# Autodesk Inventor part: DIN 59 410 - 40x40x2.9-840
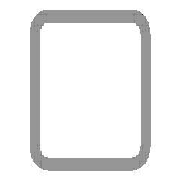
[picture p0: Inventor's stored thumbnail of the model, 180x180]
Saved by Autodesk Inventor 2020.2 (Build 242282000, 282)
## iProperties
Manager: www.cadconsulting.pl
Company: Fabian Stasiak CAD Consulting
_CCFamilyMember: 10
_CCFamilyDisplayName: DIN 59410 (Kwadrat) - Rurki stalowe o przekroju kwadratowym formowane na gorąco
_FrameMemberDoc: Frame Member File
_Version: 15.0.0
_GetPNFromCC: 1
Created: 2015-01
Part Number: DIN 59 410 - 40x40x2.9-840
Material: Stal, miękka
Description: Rurki stalowe o przekroju kwadratowym formowane na gorąco
Document SubType Name: Modellieren
Standard: DIN
Designer: F.Stasiak
Standards Organization: DIN
Language: pl-PL
Size Designation: 40x40x2.9
Categories: <MemberInstance><Categories><Category DisplayName="Kształtowniki konstrukcyjne" InternalName="089c4875-fa83-4c05-b084-43b9cc11f5ed" Mnemonic="GRDR"><CategoryPar
Stock Number: 40x40x2.9
Density: 7.85 g/cm^3
Appearance: Częściowo polerowana
Catalog Web Link: www.expertbooks.pl
IsCustomPart: 1
G_L: 840,000 mm
G_W: 40,000 mm
G_H: 40,000 mm
Author: F.Stasiak
Subject: Zbiór ćwiczeń. Autodesk Inventor 2020. Kurs Professional
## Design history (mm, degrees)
node "Płaszczyzna początkowa"
node "Płaszczyzna końcowa"
sketch "Szkic"
  geometry: L1 (-14.2, 20)-(14.2, 20); L2 (20, 14.2)-(20, -14.2); L3 (14.2, -20)-(-14.2, -20); L4 (-20, -14.2)-(-20, 14.2); L5 (-29.682, 0)-(29.682, 0) reference; L6 (0, -29.682)-(0, 29.682) reference; L7 (-14.2, 17.1)-(14.2, 17.1); L8 (17.1, 14.2)-(17.1, -14.2); L9 (14.2, -17.1)-(-14.2, -17.1); L10 (-17.1, -14.2)-(-17.1, 14.2); A1 r 5.8 centre (-14.2, 14.2) between (-14.2, 20) and (-20, 14.2); A2 r 5.8 centre (14.2, 14.2) between (20, 14.2) and (14.2, 20); A3 r 5.8 centre (14.2, -14.2) between (14.2, -20) and (20, -14.2); A4 r 5.8 centre (-14.2, -14.2) between (-20, -14.2) and (-14.2, -20); A5 r 2.9 centre (-14.2, 14.2) between (-14.2, 17.1) and (-17.1, 14.2); A6 r 2.9 centre (14.2, 14.2) between (17.1, 14.2) and (14.2, 17.1); A7 r 2.9 centre (14.2, -14.2) between (14.2, -17.1) and (17.1, -14.2); A8 r 2.9 centre (-14.2, -14.2) between (-17.1, -14.2) and (-14.2, -17.1); 3 further points
  constraints: 16 end point, 16 point on circle, 8 centre point, 8 tangent, 6 point on line, 4 parallel, 3 equal radius, 3 perpendicular, 1 horizontal, 7 other
  dimensions: "b" = 40 distance of point (-20, 20) point (20, 20); "msp_r" = 5.8 radius of A1 (= 2 x ParT); "d8" = 20 distance between parallel lines of L4 L6 (= d9); "d9" = 20 distance between parallel lines of L3 L5 (= 0.5 x b); "d10" = 2.9 distance between parallel lines of L3 L9 (= ParT)
extrude "Bryła" new body sketch "Szkic" taper "d4" = 0 deg; stored distance "NLG" = 10
node "Driven Length"
  sketch "Sketch2"
    geometry: L1 (0, 0)-(10, 0) reference
    constraints: 2 end point, 1 horizontal
  workplane "Work Plane3"
  sketch "Sketch3"
    geometry: L1 (-2, -20)-(12, -20) reference; L2 (-2, 820)-(12, 820) reference
    dimensions: "d14" = 840 distance between parallel lines of L1 L2 (derived)
node "Płaszczyzna konstrukcyjna4"
feature "Podział1"
node "Płaszczyzna konstrukcyjna5"
feature "Podział2"
body "Solid1"
other parameters: "ParT" = 2.9, "G_L" = 840 (= d14) [user parameter], "d13" = 90 deg
